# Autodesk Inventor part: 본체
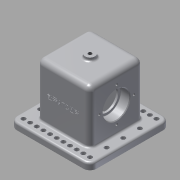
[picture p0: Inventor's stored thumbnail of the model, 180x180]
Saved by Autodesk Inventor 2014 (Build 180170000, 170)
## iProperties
Created: 2018-11
Part Number: 본체
Material: 알루미늄 6061
Document SubType Name: Modeling
Designer: kh
Mass: 1022.62 g
Surface Area: 782.359 cm^2
Volume: 377.352 cm^3
Density: 2.71 g/cm^3
Appearance: 알루미늄 - 평지
Author: kh
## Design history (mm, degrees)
sketch "스케치1"
  geometry: L1 (-60, -60)-(60, -60); L2 (60, -60)-(60, 60); L3 (60, 60)-(-60, 60); L4 (-60, 60)-(-60, -60); L5 (-60, -60)-(60, 60); L6 (60, -60)-(-60, 60); 1 further point
  constraints: 12 end point, 2 midpoint, 2 parallel, 1 horizontal, 1 perpendicular
  dimensions: "d0" = 120 distance of L3.end L2.end; "d1" = 120 distance of L2.end L1.end
extrude "돌출1" new body sketch "스케치1" distance "d2" = 10; taper "d3" = 0 deg
sketch "스케치2"
  geometry: L1 (40, -40)-(-40, -40); L2 (-40, -40)-(-40, 40); L3 (-40, 40)-(40, 40); L4 (40, 40)-(40, -40); L5 (40, -40)-(-40, 40); L6 (-40, -40)-(40, 40); 1 further point
  constraints: 12 end point, 2 midpoint, 2 parallel, 1 horizontal, 1 perpendicular
  dimensions: "d4" = 80 distance of L2.end L3.end; "d5" = 80 distance of L1.end L2.end
extrude "돌출2" join sketch "스케치2" distance "d6" = 90; taper "d7" = 0 deg
sketch "스케치3"
  geometry: C1 r 7.5 at (0, 0); 1 further point
  constraints: 1 centre point, 1 coincident
  dimensions: "d8" = 15 diameter of C1
extrude "돌출3" join sketch "스케치3" distance "d9" = 5; taper "d10" = 0 deg
sketch "스케치4"
  geometry: L1 (23, 30)-(-23, 30); L2 (-23, 30)-(-23, -30); L3 (-23, -30)-(23, -30); L4 (23, -30)-(23, 30); L5 (23, 30)-(-23, -30); L6 (-23, 30)-(23, -30); 1 further point
  constraints: 12 end point, 2 midpoint, 2 parallel, 1 horizontal, 1 perpendicular
  dimensions: "d11" = 46 distance of L2.end L3.end; "d12" = 60 distance of L1.end L2.end
extrude "돌출4" cut sketch "스케치4" distance "d13" = 80; taper "d14" = 0 deg
sketch "스케치5"
  geometry: L1 (-10, 100)-(-10, -20) reference; L2 (-10, 40)-(114.285, 40); C1 r 20 at (38, 40)
  constraints: 2 end point, 1 centre point, 1 perpendicular, 1 point on line
  dimensions: "d15" = 40 diameter of C1; "d16" = 48 distance from line of L1 C1.centre
extrude "돌출5" cut sketch "스케치5" distance "d17" = 14; taper "d18" = 0 deg
sketch "스케치6" dims "d19" = 52
  geometry: L1 (38, 40)-(64, 40); C1 r 20 at (38, 40) reference; 2 further points
  constraints: 2 end point, 1 coincident, 1 horizontal, 1 horizontal alignment, 3 other
hole "구멍1" sketch "스케치6" at (64, 40) diameter "d20" = 3.459; stored, may be unused: countersink angle "d24" = 90 deg, drill point angle "d26" = 118 deg; dims "d21" = 8, "d22" = 4, "d23" = 2, "d25" = 10
sketch "스케치7"
  geometry: C1 r 16.5 at (0, 0); C2 r 20 at (0, 0) reference; 1 further point
  constraints: 1 centre point, 1 concentric
  dimensions: "d30" = 33 diameter of C1
extrude "돌출6" cut sketch "스케치7" stored distance "d31" = 14; taper "d32" = 0 deg
hole "구멍2" diameter "d35" = 5.459; stored, may be unused: countersink angle "d39" = 90 deg, drill point angle "d41" = 0 deg; dims "d33" = 10, "d34" = 10, "d36" = 8, "d37" = 4, "d38" = 2, "d40" = 10
sketch "스케치8"
  geometry: 2 further points
  dimensions: "d42" = 50 horizontal distance of point (-50, 50) point (0, 0); "d43" = 50 horizontal distance of point (0, 0) point (-50, 50)
hole "구멍3" sketch "스케치8" at (-50, 50) diameter "d44" = 6.6; stored, may be unused: countersink angle "d48" = 90 deg, drill point angle "d50" = 0 deg; dims "d45" = 8, "d46" = 4, "d47" = 2, "d49" = 10
fillet "모깎기1" dims "d57" = 10, "d58" = 8, "d59" = 3
fillet "모깎기2" dims "d60" = 3
fillet "모깎기3" dims "d61" = 8
chamfer "모따기1" distance "d62" = 1; stored, may be unused: second distance "d63" = 2, angle "d64" = 45 deg
fillet "모깎기4" dims "d65" = 0.6
fillet "모깎기5" dims "d66" = 3
fillet "모깎기6" dims "d67" = 3
node "작업 평면1"
sketch "스케치9"
  geometry: L1 (7.907, 38.491)-(56.093, 38.491); L2 (56.093, 38.491)-(56.093, 31.509); L3 (56.093, 31.509)-(7.907, 31.509); L4 (7.907, 31.509)-(7.907, 38.491); L5 (7.907, 35)-(56.093, 35); L6 (32, 38.491)-(32, 31.509); L7 (32, -13)-(32, 76.221); L8 (-18, -13)-(82, -13) reference
  constraints: 6 end point, 4 midpoint, 2 collinear, 1 vertical, 2 other
  dimensions: "d69" = 48 distance between parallel lines of L8 L5
feature "엠보싱1" sketch "스케치9" dims "d0" = 120, "d1" = 120, "d70" = 0.5, "d71" = 0
fillet "모깎기7" dims "d72" = 3
node "솔리드1"
pattern_circular "원형 패턴1" dims angle "d28" = 360 deg
mirror "대칭1"
pattern_linear "직사각형 패턴1" dims "d53" = 10
pattern_linear "직사각형 패턴2" dims "d56" = 25
mirror "대칭2"
mirror "대칭3"
other parameters: "d68" = 34
